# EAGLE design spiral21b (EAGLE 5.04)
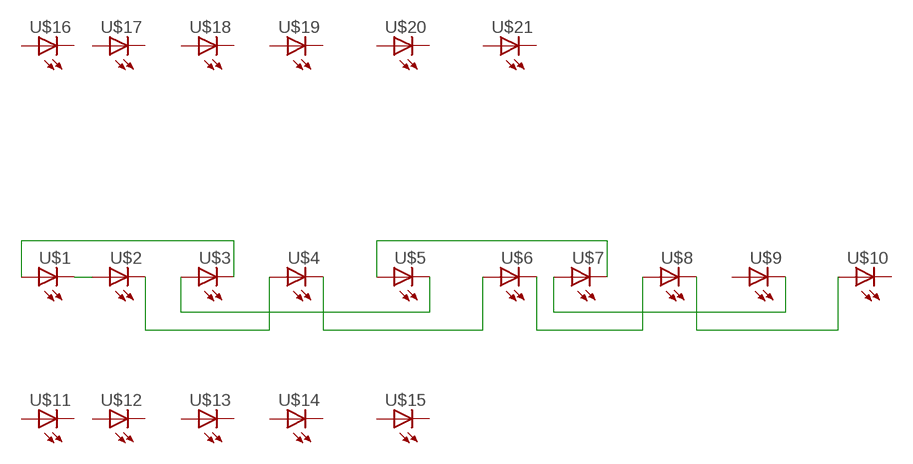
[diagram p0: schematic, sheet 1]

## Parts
U$1  LED5MM  [LED5MM]
U$2  LED5MM  [LED5MM]
U$3  LED5MM  [LED5MM]
U$4  LED5MM  [LED5MM]
U$5  LED5MM  [LED5MM]
U$6  LED5MM  [LED5MM]
U$7  LED5MM  [LED5MM]
U$8  LED5MM  [LED5MM]
U$9  LED5MM  [LED5MM]
U$10  LED5MM  [LED5MM]
U$11  LED5MM  [LED5MM]
U$12  LED5MM  [LED5MM]
U$13  LED5MM  [LED5MM]
U$14  LED5MM  [LED5MM]
U$15  LED5MM  [LED5MM]
U$16  LED5MM  [LED5MM]
U$17  LED5MM  [LED5MM]
U$18  LED5MM  [LED5MM]
U$19  LED5MM  [LED5MM]
U$20  LED5MM  [LED5MM]
U$21  LED5MM  [LED5MM]

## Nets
N$1: U$1.K(C) U$2.A
N$2: U$2.K(C) U$4.A
N$3: U$4.K(C) U$6.A
N$4: U$6.K(C) U$8.A
N$5: U$8.K(C) U$10.A
N$6: U$1.A U$3.K(C)
N$7: U$3.A U$5.K(C)
N$8: U$5.A U$7.K(C)
N$9: U$7.A U$9.K(C)
Unconnected: U$9.A U$10.K(C) U$11.A U$11.K(C) U$12.A U$12.K(C) U$13.A U$13.K(C) U$14.A U$14.K(C) U$15.A U$15.K(C) U$16.A U$16.K(C) U$17.A U$17.K(C) U$18.A U$18.K(C) U$19.A U$19.K(C) U$20.A U$20.K(C) U$21.A U$21.K(C)

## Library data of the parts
U$1-U$21 = led(2):LED: LED

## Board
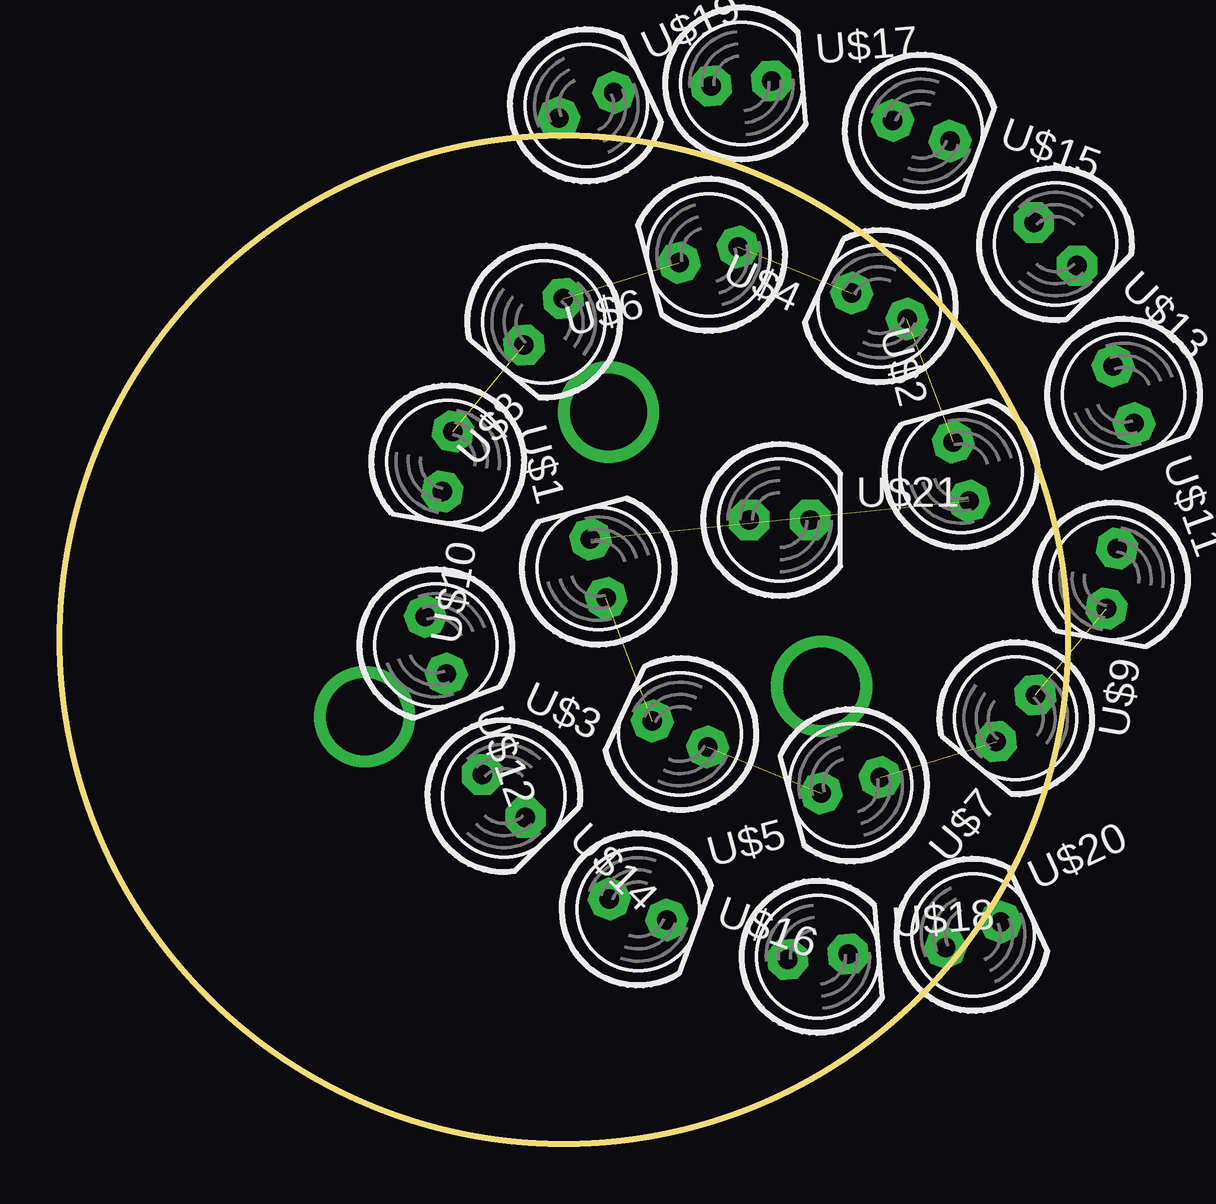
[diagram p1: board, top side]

Size 42 x 42 mm. Coordinates in mm from the lower left corner, seen from the top.
Outline: circle at 21,21 radius 21
Copper layers (1*16): Top 0.035mm / dielectric 1.5mm / Bottom 0.035mm
Design rules "default": minimum track width 10mil, minimum drill 24mil, track to track 8mil, track to pad 8mil, pad to pad 8mil, via to via 8mil, smd to smd 8mil, copper to edge 40mil, drill to drill 8mil, minimum pad ring 10mil, minimum via ring 8mil, stop-mask expansion 4mil, vias tented up to drill 0mil, thermal gap 10mil

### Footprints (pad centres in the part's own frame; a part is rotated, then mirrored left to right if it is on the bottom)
LED5MM = drill 0.813 pad 1.676 octagon: A -1.27,0; K 1.27,0

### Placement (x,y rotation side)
U$1  22.44,23.95 104.9 top
U$2  37.56,28.01 104.9 top
U$3  25.84,17.07 155 top
U$4  34.16,34.89 155 top
U$5  32.96,14.93 195 top
U$6  27.04,37.03 195 top
U$7  39.84,17.72 230 top
U$8  20.16,34.24 230 top
U$9  43.84,23.54 260 top
U$10  16.16,28.42 260 top
U$11  44.33,31.2 290 top
U$12  15.67,20.76 290 top
U$13  41.5,37.48 315 top
U$14  18.5,14.48 315 top
U$15  35.9,42.2 340 top
U$16  24.1,9.76 340 top
U$17  28.41,44.18 4.9 top
U$18  31.59,7.78 4.9 top
U$19  21.94,43.26 25 top
U$20  38.06,8.7 25 top
U$21  30,25.98 0 top

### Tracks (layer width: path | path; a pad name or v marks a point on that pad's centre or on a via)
N$1  (1 unrouted)
N$2  (1 unrouted)
N$3  (1 unrouted)
N$4  (1 unrouted)
N$5  (1 unrouted)
N$6  (1 unrouted)
N$7  (1 unrouted)
N$8  (1 unrouted)
N$9  (1 unrouted)
N$10  (via drill 3.2)
  other vias: 22.86,30.48
N$11  (via drill 3.2)
  other vias: 12.7,17.78
N$12  (via drill 3.2)
  other vias: 31.75,19.05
